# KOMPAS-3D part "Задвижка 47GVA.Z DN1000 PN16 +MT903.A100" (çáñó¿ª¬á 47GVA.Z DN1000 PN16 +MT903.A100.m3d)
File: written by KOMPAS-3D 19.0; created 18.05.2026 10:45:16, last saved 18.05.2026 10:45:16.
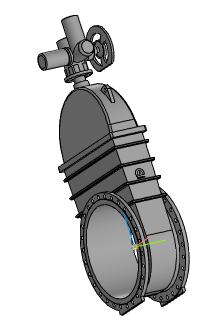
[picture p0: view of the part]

Document properties: Автор: Энергия; Полное имя файла: ..\Задвижка 47GVA.Z DN350_DN1200+MT903.A\Задвижка 47GVA.Z DN1000 PN16 +MT903.A100.a3d

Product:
- Part/product: Задвижка 47GVA.Z DN1000 PN16 +MT903.A100
    Масса: 4863.68
  - Body: Электропривод МТ903.А100 без блока управления
      Масса: 346.451
  - Body: Задвижка 47GVA.Z DN1000 PN16 без исполнит. мех.
      Масса: 4517.22

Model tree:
1. Операция без истории:1
2. Операция без истории:2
